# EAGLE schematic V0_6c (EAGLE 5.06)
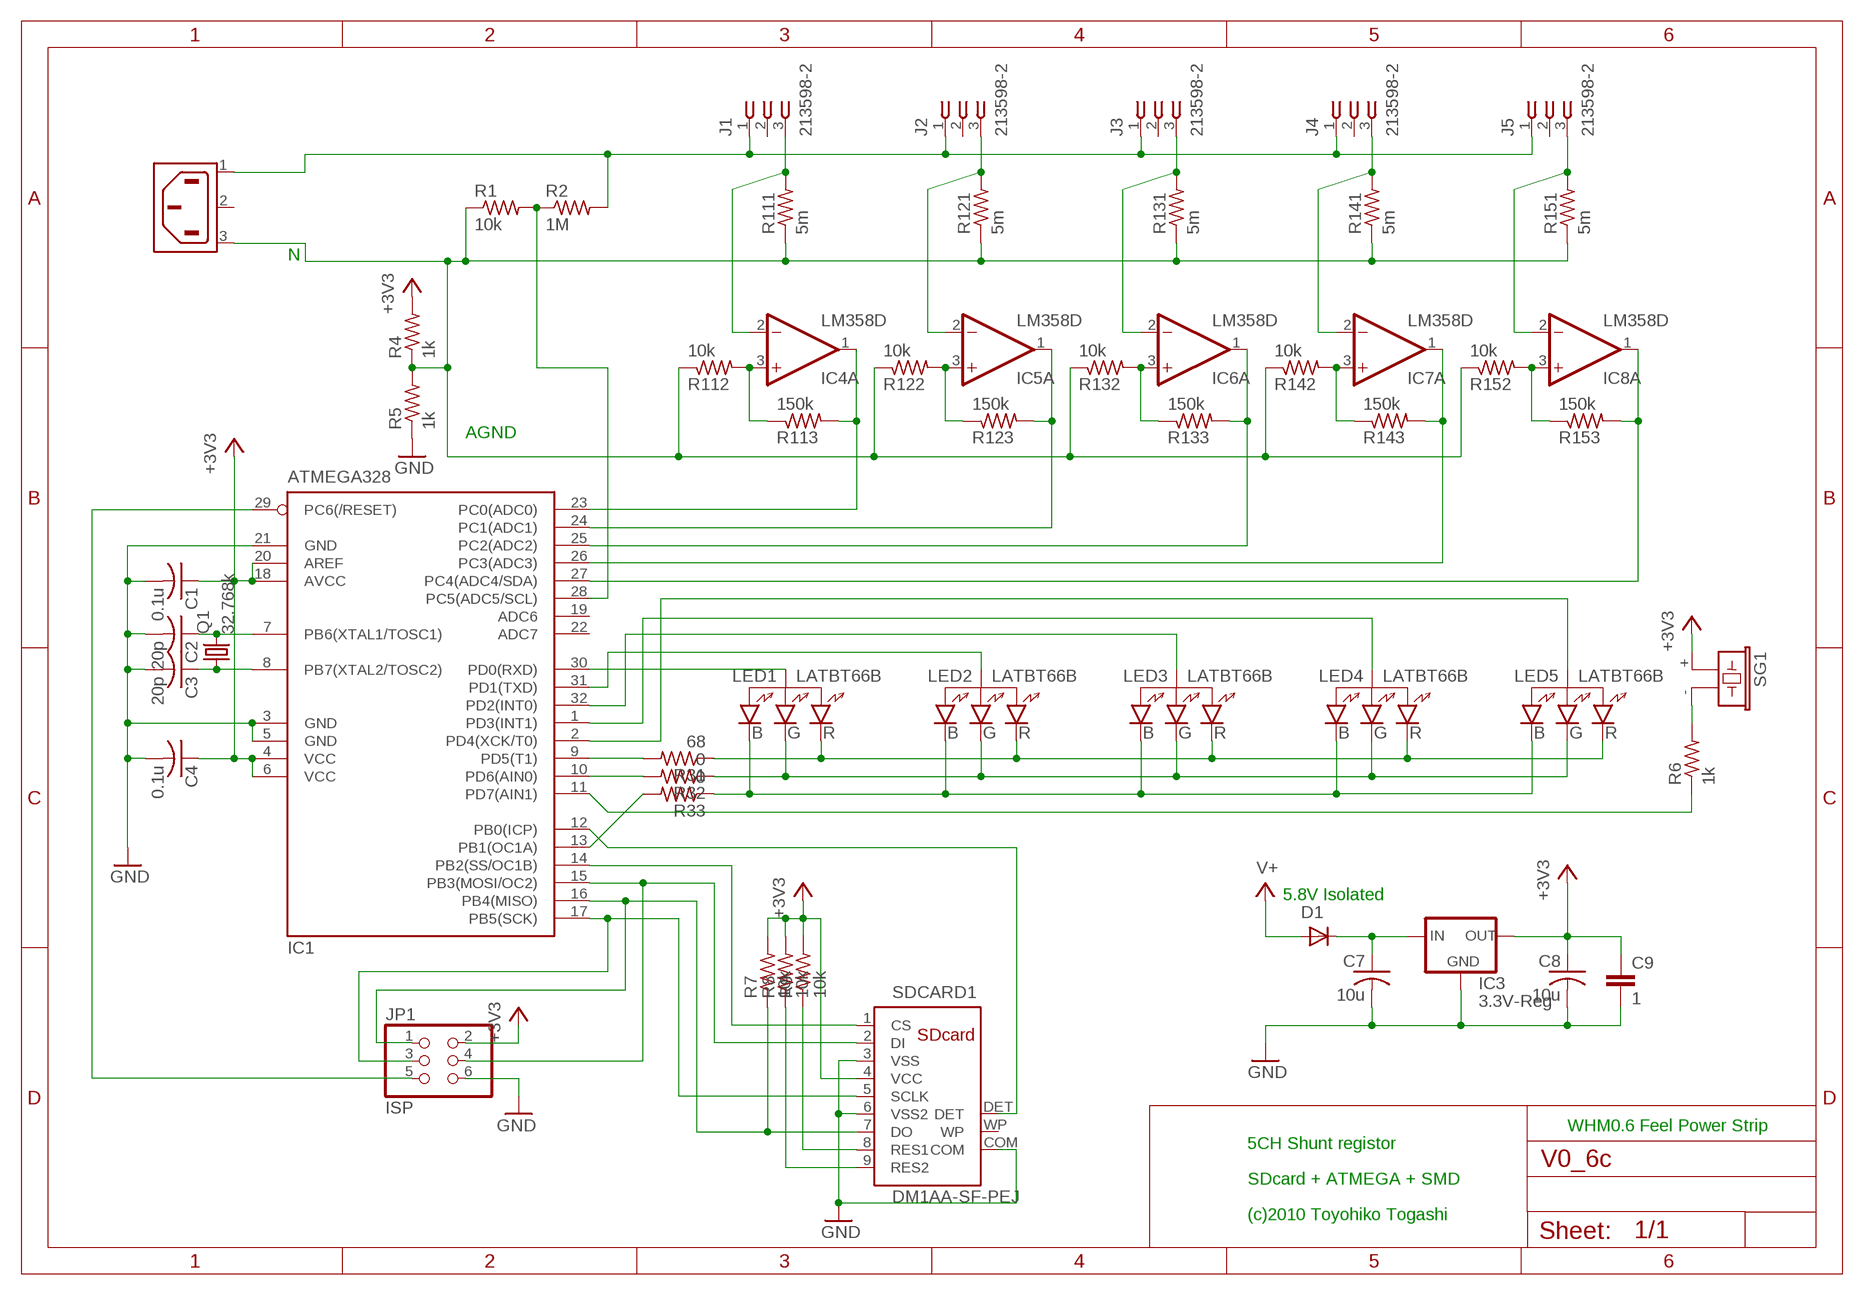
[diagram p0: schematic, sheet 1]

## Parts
C1  0.1u  C-USC0603  [C0603]
C2  20p  C-USC0603  [C0603]
C3  20p  C-USC0603  [C0603]
C4  0.1u  C-USC0603  [C0603]
C7  10u  C-USC0603  [C0603]
C8  10u  C-USC0603  [C0603]
C9  1  C7.5/4  [C7.5B4]
D1  GF1  [SMA-DO214AC]
IC1  ATMEGA328  MEGA8-AI  [TQFP32-08]
IC3  3.3V-Reg  XC63FPM  [SOT23]
IC4  LM358D  [SO08]
IC5  LM358D  [SO08]
IC6  LM358D  [SO08]
IC7  LM358D  [SO08]
IC8  LM358D  [SO08]
J1  213598-2  [213598-2]
J2  213598-2  [213598-2]
J3  213598-2  [213598-2]
J4  213598-2  [213598-2]
J5  213598-2  [213598-2]
JP1  ISP  PINHD-2X3  [2X03]
LED1  LATBT66B  [P-LCC-4]
LED2  LATBT66B  [P-LCC-4]
LED3  LATBT66B  [P-LCC-4]
LED4  LATBT66B  [P-LCC-4]
LED5  LATBT66B  [P-LCC-4]
Q1  32.768k  CRYSTALHC49UP  [HC49UP]
R1  10k  R-US_R0603  [R0603]
R2  1M  R-US_R0603  [R0603]
R4  1k  R-US_R0603  [R0603]
R5  1k  R-US_R0603  [R0603]
R6  1k  R-US_R0603  [R0603]
R7  10k  R-US_R0603  [R0603]
R8  10k  R-US_R0603  [R0603]
R9  10k  R-US_R0603  [R0603]
R31  68  R-US_R0603  [R0603]
R32  0  R-US_R0603  [R0603]
R33  0  R-US_R0603  [R0603]
R111  5m  R-US_R3225  [R3225]
R112  10k  R-US_R0603  [R0603]
R113  150k  R-US_R0603  [R0603]
R121  5m  R-US_R3225  [R3225]
R122  10k  R-US_R0603  [R0603]
R123  150k  R-US_R0603  [R0603]
R131  5m  R-US_R3225  [R3225]
R132  10k  R-US_R0603  [R0603]
R133  150k  R-US_R0603  [R0603]
R141  5m  R-US_R3225  [R3225]
R142  10k  R-US_R0603  [R0603]
R143  150k  R-US_R0603  [R0603]
R151  5m  R-US_R3225  [R3225]
R152  10k  R-US_R0603  [R0603]
R153  150k  R-US_R0603  [R0603]
SDCARD1  DM1AA-SF-PEJ  [DM1AA]
SG1  F/CM12P  [F/CM12P]
X1  6ESRM-P  [6ESRM-P]

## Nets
+3V3: C1.1 C4.1 C8.1 C9.1 IC1.4(VCC) IC1.6(VCC) IC1.18(AVCC) IC1.20(AREF) IC3.2(OUT) JP1.2 R4.2 R7.2 R8.2 R9.2 SDCARD1.4(VCC) SG1.+
GND: C1.2 C2.2 C3.2 C4.2 C7.2 C8.2 C9.2 IC1.3(GND) IC1.5(GND) IC1.21(GND) IC3.1(GND) JP1.6 R5.1 SDCARD1.3(VSS) SDCARD1.6(VSS2) SDCARD1.COM
N$1: R1.1 R4.1 R5.2 R111.1 R112.1 R121.1 R122.1 R131.1 R132.1 R141.1 R142.1 R151.1 R152.1 X1.3(AC2)
N$2: IC1.28(PC5(ADC5/SCL)) R1.2 R2.1
N$3: IC4.2(A:-IN) J1.3 R111.2
N$4: IC5.2(A:-IN) J2.3 R121.2
N$5: IC1.24(PC1(ADC1)) IC5.1(A:OUT) R123.2
N$7: C2.1 IC1.7(PB6(XTAL1/TOSC1)) Q1.2
N$9: IC1.29(PC6(/RESET)) JP1.5
N$10: IC1.9(PD5(T1)) R31.2
N$11: C3.1 IC1.8(PB7(XTAL2/TOSC2)) Q1.1
N$14: IC1.31(PD1(TXD)) LED2.P$2
N$15: IC1.30(PD0(RXD)) LED1.P$2
N$16: IC1.32(PD2(INT0)) LED3.P$2
N$17: IC1.17(PB5(SCK)) JP1.3 SDCARD1.5(SCLK)
N$18: IC1.1(PD3(INT1)) LED4.P$2
N$19: IC4.3(A:+IN) R112.2 R113.1
N$20: IC5.3(A:+IN) R122.2 R123.1
N$21: IC1.11(PD7(AIN1)) R6.1
N$22: IC1.2(PD4(XCK/T0)) LED5.P$2
N$23: IC1.23(PC0(ADC0)) IC4.1(A:OUT) R113.2
N$26: R6.2 SG1.-
N$28: LED1.P$1 LED2.P$1 LED3.P$1 LED4.P$1 LED5.P$1 R31.1
N$29: IC6.3(A:+IN) R132.2 R133.1
N$30: LED1.P$4 LED2.P$4 LED3.P$4 LED4.P$4 LED5.P$4 R32.1
N$31: LED1.P$3 LED2.P$3 LED3.P$3 LED4.P$3 LED5.P$3 R33.1
N$32: IC1.15(PB3(MOSI/OC2)) JP1.4 SDCARD1.2(DI)
N$33: IC1.16(PB4(MISO)) JP1.1 R7.1 SDCARD1.7(DO)
N$34: IC6.2(A:-IN) J3.3 R131.2
N$35: IC1.13(PB1(OC1A)) R33.2
N$38: IC7.3(A:+IN) R142.2 R143.1
N$39: IC1.14(PB2(SS/OC1B)) SDCARD1.1(CS)
N$40: J1.1 J2.1 J3.1 J4.1 J5.1 R2.2 X1.1(AC1)
N$41: R8.1 SDCARD1.9(RES2)
N$42: R9.1 SDCARD1.8(RES1)
N$43: IC1.12(PB0(ICP)) SDCARD1.DET
N$44: IC7.2(A:-IN) J4.3 R141.2
N$47: IC1.10(PD6(AIN0)) R32.2
N$48: IC8.3(A:+IN) R152.2 R153.1
N$49: IC8.2(A:-IN) J5.3 R151.2
N$52: IC1.25(PC2(ADC2)) IC6.1(A:OUT) R133.2
N$53: IC1.26(PC3(ADC3)) IC7.1(A:OUT) R143.2
N$54: IC1.27(PC4(ADC4/SDA)) IC8.1(A:OUT) R153.2
N$56: C7.1 D1.K(C) IC3.3(IN)
V+: D1.A
Unconnected: IC1.19(ADC6) IC1.22(ADC7) IC4.5(B:+IN) IC4.6(B:-IN) IC4.7(B:OUT) IC5.5(B:+IN) IC5.6(B:-IN) IC5.7(B:OUT) IC6.5(B:+IN) IC6.6(B:-IN) IC6.7(B:OUT) IC7.5(B:+IN) IC7.6(B:-IN) IC7.7(B:OUT) IC8.5(B:+IN) IC8.6(B:-IN) IC8.7(B:OUT) J1.2 J2.2 J3.2 J4.2 J5.2 SDCARD1.WP X1.2(SH)

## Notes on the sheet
- N
- AGND
- 5.8V Isolated
- WHM0.6 Feel Power Strip
- 5CH Shunt registor
- SDcard + ATMEGA + SMD
- (c)2010 Toyohiko Togashi

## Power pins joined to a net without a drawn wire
V+: IC4.8(P:V+) IC5.8(P:V+) IC6.8(P:V+) IC7.8(P:V+) IC8.8(P:V+)
V-: IC4.4(P:V-) IC5.4(P:V-) IC6.4(P:V-) IC7.4(P:V-) IC8.4(P:V-)

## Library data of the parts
C1-C4 C7 C8 = rcl:C-US: CAPACITOR, American symbol
C9 = capacitor-wima:C: CAPACITOR
D1 = diode:GF1: DIODE
IC1 = atmel:MEGA8: MICROCONTROLLER 8 Kbytes FLASH, 1 kbytes SRAM, 512 bytes EEPROM, USART, 6-channel 10 bit ADC, 2-channel 8 bit ADC Pin compatible with Atmega48, ATMega88, ATMega168 Source: avr.lbr
IC3 = v-reg:XC63FP: Positiv Voltage Regulators www.torex.co.jp/english/product/pro02/pdf/0201_xc62fp.pdf
IC4-IC8 = linear:LM358: OP AMP also LM158; LM258; LM2904 Source: http://cache.national.com/ds/LM/LM158.pdf
J1-J5 = con-amp:213598-2: AC Jack Source: ENG_CD_213598_M.pdf
JP1 = pinhead:PINHD-2X3: PIN HEADER
LED1-LED5 = TOG:LATBT66B: RGB LED SMD
Q1 = crystal:CRYSTAL: CRYSTAL
R1 R2 R4-R9 R31-R33 R111-R113 R121-R123 R131-R133 R141-R143 R151-R153 = rcl:R-US_: RESISTOR, American symbol
SDCARD1 = TOG:DM1AA-SF-PEJ: SDcard connector HIROSE
SG1 = buzzer:F/CM12P: BUZZER
X1 = con-tycoelectronics:6ESRM-P: AC Connector 120/250 VAC Source: http://catalog.tycoelectronics.com .. ENG_DS_1654001_1099_SR_0406.pdf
